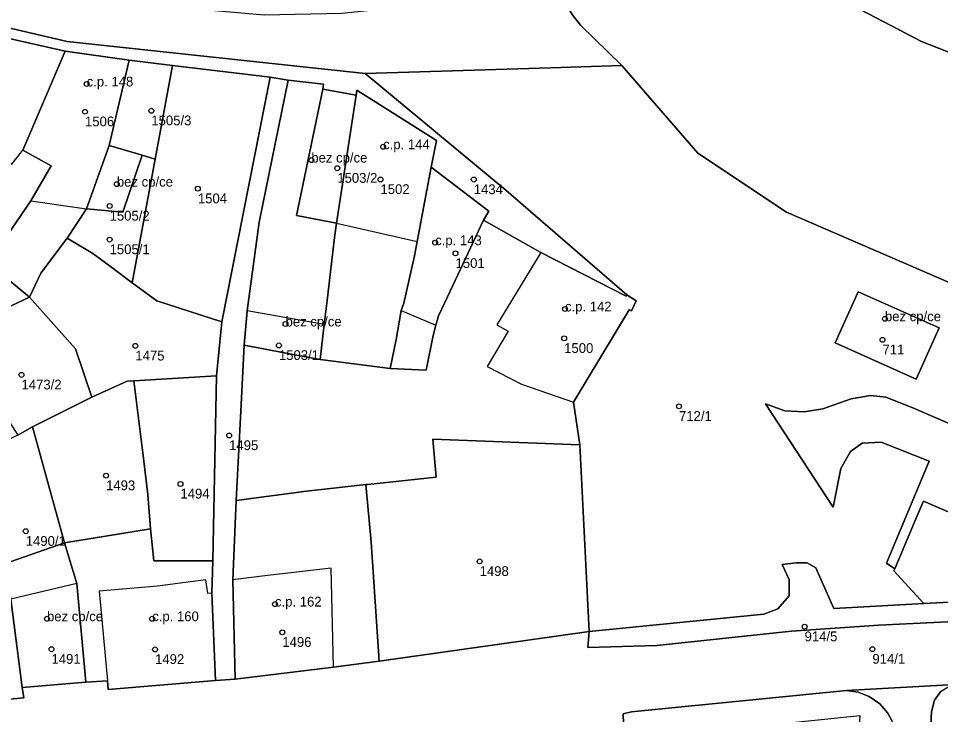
# Model space of a CAD drawing. Extents: x -878211 to -870363, y -1058464 to -1052522.
# Drawn here: x -874764.7 to -874670.5, y -1056309.4 to -1056238.3 of the extents above; entities that cross this region are included whole.
import ezdxf

# ---------------------------------------------------------------- set-up
doc = ezdxf.new("R2010")
doc.units = 0
for name, color, linetype in [('Vrstva 50', 7, 'Continuous'), ('Vrstva 51', 7, 'Continuous'), ('Vrstva 52', 7, 'Continuous')]:
    doc.layers.add(name, color=color, linetype=linetype)

msp = doc.modelspace()

# ---------------------------------------------------------------- linework, layer by layer
at = {"layer": 'Vrstva 50'}
for centre in [(-874757.7, -1056244.99994), (-874757.87, -1056247.82994), (-874751.1, -1056247.72994), (-874727.44, -1056251.40994), (-874734.77, -1056252.76994), (-874732.12, -1056253.59994), (-874727.71, -1056254.74994), (-874718.19, -1056254.75994), (-874754.62, -1056255.22994), (-874746.35, -1056255.68994), (-874755.36, -1056257.45994), (-874755.36, -1056260.88994), (-874722.13, -1056261.20994), (-874720.05, -1056262.29994), (-874708.88, -1056267.97994), (-874676.22, -1056268.97994), (-874737.4, -1056269.50994), (-874752.73, -1056271.74994), (-874738.08, -1056271.69994), (-874708.96, -1056270.97994), (-874676.47, -1056271.12994), (-874764.35, -1056274.70994), (-874697.24, -1056277.91994), (-874743.16, -1056280.89994), (-874755.72, -1056284.99994), (-874748.13, -1056285.84994), (-874763.92, -1056290.67994), (-874717.59, -1056293.75994), (-874738.48, -1056298.11994), (-874761.75, -1056299.61994), (-874751.01, -1056299.61994), (-874737.73, -1056300.99994), (-874684.42, -1056300.42994), (-874761.29, -1056302.72994), (-874750.72, -1056302.74994), (-874677.5, -1056302.71994)]:
    msp.add_circle(centre, 0.25, dxfattribs=at)
at = {"layer": 'Vrstva 51'}
for points in [[(-874779.01, -1056127.66), (-874780.45, -1056125.66), (-874793.17, -1056142.82), (-874792.46, -1056145.61), (-874788.37, -1056151.02), (-874786.78, -1056152.78), (-874770.12, -1056174.96), (-874761.29, -1056185.88), (-874747.51, -1056199.34), (-874747.04, -1056199.75), (-874740.87, -1056205.06), (-874728.32, -1056215.02), (-874719.92, -1056223.09), (-874716.4, -1056226.65), (-874716.73, -1056226.96), (-874713.06, -1056230.64), (-874711.1, -1056232.84), (-874708.16, -1056237.89), (-874707.28, -1056238.99), (-874703.07, -1056243.11), (-874695.31, -1056252.07), (-874686.26, -1056258.1), (-874668.18, -1056265.93)], [(-874664.15, -1056243.93), (-874672.49, -1056240.67), (-874680.25, -1056236.62), (-874679.58, -1056235.37), (-874681, -1056234.34), (-874681.77, -1056235.77), (-874686.72, -1056232.64), (-874692.16, -1056227.35), (-874692.89, -1056226.46), (-874696.8, -1056221.69), (-874698.33, -1056219.5), (-874701.45, -1056216.12), (-874704.89, -1056212.69), (-874716.6, -1056202), (-874718.85, -1056200.03), (-874730.46, -1056190.6), (-874737.21, -1056184.7), (-874741.58, -1056180.59), (-874749.63, -1056171.52), (-874755.19, -1056164.59)], [(-874666.81, -1056232.19), (-874672.71, -1056232.05), (-874675.44, -1056231.54), (-874681.17, -1056228.78), (-874687.74, -1056224.74), (-874687.96, -1056222.51), (-874692.89, -1056226.46), (-874692.16, -1056227.35), (-874686.72, -1056232.64), (-874681.77, -1056235.77), (-874681, -1056234.34), (-874679.58, -1056235.37), (-874680.25, -1056236.62), (-874672.49, -1056240.67), (-874664.15, -1056243.93)], [(-874773.13, -1056237.53), (-874759.69, -1056240.67), (-874729.27, -1056243.94), (-874710.36, -1056243.35), (-874703.07, -1056243.11), (-874707.28, -1056238.99), (-874708.16, -1056237.89), (-874711.1, -1056232.84), (-874718.62, -1056236.45), (-874731.64, -1056237.78), (-874739.6, -1056237.96), (-874752.36, -1056236.83), (-874752.29, -1056236.15), (-874752.81, -1056235.95), (-874754.35, -1056236.17), (-874758.8, -1056235.95), (-874774.8, -1056226.8)], [(-874773.17, -1056238.64), (-874759.89, -1056241.63), (-874753.36, -1056242.58), (-874748.93, -1056243.11), (-874738.98, -1056244.31), (-874737.15, -1056244.59), (-874733.54, -1056245.03), (-874733.6, -1056245.52), (-874730.2, -1056246.13), (-874730.12, -1056245.64), (-874721.98, -1056250.78), (-874722.55, -1056253.48), (-874716.65, -1056258), (-874717.19, -1056258.9), (-874711.34, -1056262.22), (-874702.64, -1056266.68), (-874702.55, -1056266.54), (-874714.91, -1056255.85), (-874729.27, -1056243.94), (-874759.69, -1056240.67), (-874773.13, -1056237.53)], [(-874668.18, -1056265.93), (-874686.26, -1056258.1), (-874695.31, -1056252.07), (-874703.07, -1056243.11), (-874710.36, -1056243.35), (-874729.27, -1056243.94), (-874714.91, -1056255.85), (-874702.55, -1056266.54), (-874701.61, -1056267.14), (-874702.1, -1056268.15), (-874702.32, -1056268.08), (-874708, -1056277.51), (-874707.37, -1056281.87), (-874706.42, -1056300.93), (-874688.58, -1056299.15), (-874687.15, -1056298.61), (-874686.01, -1056297.27), (-874686, -1056295.62), (-874686.71, -1056294.06), (-874685.26, -1056293.92), (-874684.17, -1056293.92), (-874683.29, -1056294.42), (-874681.42, -1056298.57), (-874672.26, -1056298.07), (-874675.3, -1056294.74), (-874675.22, -1056294.52), (-874676.05, -1056293.93), (-874671.71, -1056283.52), (-874676.6, -1056281.57), (-874678.55, -1056281.69), (-874679.75, -1056282.55), (-874680.71, -1056284.28), (-874681.49, -1056288.21), (-874688.4, -1056277.65), (-874686.45, -1056278.37), (-874684.45, -1056278.49), (-874682.55, -1056278.16), (-874679.67, -1056277.16), (-874677.7, -1056276.8), (-874676.13, -1056276.98), (-874673.36, -1056278.07), (-874669.06, -1056279.94)], [(-874669.06, -1056279.94), (-874673.36, -1056278.07), (-874676.13, -1056276.98), (-874677.7, -1056276.8), (-874679.67, -1056277.16), (-874682.55, -1056278.16), (-874684.45, -1056278.49), (-874686.45, -1056278.37), (-874688.4, -1056277.65), (-874681.49, -1056288.21), (-874680.71, -1056284.28), (-874679.75, -1056282.55), (-874678.55, -1056281.69), (-874676.6, -1056281.57), (-874671.71, -1056283.52), (-874676.05, -1056293.93), (-874675.22, -1056294.52), (-874672.96, -1056289.18), (-874672.29, -1056287.61), (-874662.04, -1056292.02)], [(-874665.6, -1056299.74), (-874676.84, -1056300.28), (-874685.76, -1056300.9), (-874699.51, -1056302.36), (-874706.55, -1056302.57), (-874706.42, -1056300.93), (-874727.85, -1056303.96), (-874732.52, -1056304.58), (-874742.55, -1056305.8), (-874744.54, -1056305.94), (-874755.51, -1056306.86), (-874755.58, -1056305.95), (-874757.77, -1056306.08), (-874764.27, -1056306.63), (-874764.11, -1056307.71), (-874773.64, -1056308.59), (-874777.22, -1056308.94), (-874782.12, -1056309.61)], [(-874702.87, -1056311.49), (-874702.94, -1056309.32), (-874702.09, -1056309.12), (-874680.13, -1056306.95), (-874668.48, -1056306.3)], [(-874668.48, -1056306.3), (-874680.13, -1056306.95), (-874678.94, -1056307.12), (-874677.84, -1056307.55), (-874676.75, -1056308.3), (-874675.91, -1056309.25), (-874675.49, -1056310.07)], [(-874670.03, -1056324.55), (-874671.48, -1056324.45), (-874671.44, -1056323.57), (-874671.98, -1056318.9), (-874671.48, -1056309.14), (-874671.17, -1056307.93), (-874670.54, -1056307.09)]]:
    msp.add_lwpolyline(points, dxfattribs=at)
for points in [[(-874774.24, -1056238.87), (-874775.52, -1056239.72), (-874777.2, -1056240.96), (-874773.75, -1056245.85), (-874771.66, -1056248.03), (-874773.68, -1056251.33), (-874770.95, -1056254.12), (-874768.89, -1056256.23), (-874770.94, -1056258.34), (-874771.83, -1056259.23), (-874767.75, -1056263.3), (-874765.9, -1056260.59), (-874763.4, -1056256.93), (-874761.33, -1056253.37), (-874764.21, -1056251.74), (-874759.89, -1056241.63), (-874773.17, -1056238.64)], [(-874777.2, -1056240.96), (-874783.25, -1056245.4), (-874777.38, -1056253.98), (-874766.66, -1056268.23), (-874763.52, -1056266.77), (-874767.75, -1056263.3), (-874771.83, -1056259.23), (-874770.94, -1056258.34), (-874768.89, -1056256.23), (-874770.95, -1056254.12), (-874773.68, -1056251.33), (-874771.66, -1056248.03), (-874773.75, -1056245.85)], [(-874759.89, -1056241.63), (-874764.21, -1056251.74), (-874761.33, -1056253.37), (-874763.4, -1056256.93), (-874765.9, -1056260.59), (-874767.75, -1056263.3), (-874763.52, -1056266.77), (-874762.37, -1056264.31), (-874759.7, -1056260.74), (-874757.73, -1056257.75), (-874755.42, -1056251.29), (-874753.36, -1056242.58)], [(-874753.36, -1056242.58), (-874755.42, -1056251.29), (-874752.05, -1056252.28), (-874750.7, -1056252.67), (-874748.93, -1056243.11)], [(-874750.7, -1056252.67), (-874753.04, -1056265.29), (-874750.54, -1056267.15), (-874743.89, -1056269.29), (-874738.98, -1056244.31), (-874748.93, -1056243.11)], [(-874743.89, -1056269.29), (-874744.46, -1056274.82), (-874744.84, -1056293.69), (-874744.91, -1056296.99), (-874744.54, -1056305.94), (-874742.55, -1056305.8), (-874742.79, -1056295.64), (-874742.44, -1056287.55), (-874741.96, -1056278.43), (-874741.61, -1056271.66), (-874741.31, -1056268.15), (-874740.09, -1056259.11), (-874737.15, -1056244.59), (-874738.98, -1056244.31)], [(-874736.29, -1056258.44), (-874733.6, -1056245.52), (-874733.54, -1056245.03), (-874737.15, -1056244.59), (-874740.09, -1056259.11), (-874741.31, -1056268.15), (-874741.61, -1056271.66), (-874736.08, -1056272.72), (-874733.87, -1056273.14), (-874733.46, -1056269.55), (-874733.16, -1056267.11), (-874732.39, -1056260.69), (-874732.2, -1056259.2)], [(-874730.2, -1056246.13), (-874733.6, -1056245.52), (-874736.29, -1056258.44), (-874732.2, -1056259.2)], [(-874730.2, -1056246.13), (-874732.2, -1056259.2), (-874732.39, -1056260.69), (-874733.16, -1056267.11), (-874733.46, -1056269.55), (-874733.87, -1056273.14), (-874726.73, -1056274.07), (-874726.11, -1056271.09), (-874725.59, -1056268.13), (-874725.33, -1056267.4), (-874724.25, -1056262.55), (-874723.97, -1056261.08), (-874722.55, -1056253.48), (-874721.98, -1056250.78), (-874730.12, -1056245.64)], [(-874757.73, -1056257.75), (-874754.01, -1056258.08), (-874752.05, -1056252.28), (-874755.42, -1056251.29)], [(-874752.05, -1056252.28), (-874754.01, -1056258.08), (-874757.73, -1056257.75), (-874759.7, -1056260.74), (-874757.06, -1056262.3), (-874755.13, -1056263.74), (-874753.04, -1056265.29), (-874750.7, -1056252.67)], [(-874725.59, -1056268.13), (-874726.11, -1056271.09), (-874726.73, -1056274.07), (-874723.05, -1056274.22), (-874722.35, -1056270.7), (-874722.06, -1056269.63), (-874721.79, -1056268.68), (-874720.87, -1056266.73), (-874717.19, -1056258.9), (-874716.65, -1056258), (-874722.55, -1056253.48), (-874723.97, -1056261.08), (-874724.25, -1056262.55), (-874725.33, -1056267.4)], [(-874726.73, -1056274.07), (-874733.87, -1056273.14), (-874736.08, -1056272.72), (-874741.61, -1056271.66), (-874741.96, -1056278.43), (-874742.44, -1056287.55), (-874735.25, -1056286.6), (-874733.12, -1056286.36), (-874729.2, -1056285.92), (-874729, -1056285.9), (-874722.02, -1056285.14), (-874722.37, -1056281.26), (-874707.37, -1056281.87), (-874708, -1056277.51), (-874702.32, -1056268.08), (-874702.1, -1056268.15), (-874701.61, -1056267.14), (-874702.55, -1056266.54), (-874702.64, -1056266.68), (-874711.34, -1056262.22), (-874717.19, -1056258.9), (-874720.87, -1056266.73), (-874721.79, -1056268.68), (-874722.06, -1056269.63), (-874722.35, -1056270.7), (-874723.05, -1056274.22)], [(-874762.37, -1056264.31), (-874763.52, -1056266.77), (-874758.84, -1056272.05), (-874757.19, -1056276.98), (-874753.58, -1056275.36), (-874752.88, -1056275.32), (-874744.46, -1056274.82), (-874743.89, -1056269.29), (-874750.54, -1056267.15), (-874753.04, -1056265.29), (-874755.13, -1056263.74), (-874757.06, -1056262.3), (-874759.7, -1056260.74)], [(-874767.46, -1056276.69), (-874764.73, -1056280.88), (-874763.22, -1056280.01), (-874757.19, -1056276.98), (-874758.84, -1056272.05), (-874763.52, -1056266.77), (-874766.66, -1056268.23), (-874771.33, -1056270.93)], [(-874670.68, -1056269.89), (-874673.02, -1056275.14), (-874681.3, -1056271.45), (-874678.95, -1056266.21)], [(-874670.68, -1056269.89), (-874678.95, -1056266.21), (-874681.3, -1056271.45), (-874673.02, -1056275.14)], [(-874751.45, -1056286.92), (-874751.96, -1056282.66), (-874752.88, -1056275.32), (-874753.58, -1056275.36), (-874757.19, -1056276.98), (-874763.22, -1056280.01), (-874759.98, -1056291.86), (-874751.2, -1056290.43)], [(-874744.46, -1056274.82), (-874752.88, -1056275.32), (-874751.96, -1056282.66), (-874751.45, -1056286.92), (-874751.2, -1056290.43), (-874750.84, -1056293.71), (-874744.84, -1056293.69)], [(-874764.73, -1056280.88), (-874775.27, -1056285.79), (-874774.59, -1056288.09), (-874774.04, -1056290.94), (-874772.65, -1056290.67), (-874771.32, -1056290.37), (-874771.51, -1056289.42), (-874768.96, -1056288.26), (-874769.35, -1056287.34), (-874768.05, -1056286.78), (-874766.82, -1056289.6), (-874767.89, -1056290.01), (-874766.1, -1056294), (-874759.98, -1056291.86), (-874763.22, -1056280.01)], [(-874729.2, -1056285.92), (-874728.66, -1056291.78), (-874727.85, -1056303.96), (-874706.42, -1056300.93), (-874707.37, -1056281.87), (-874722.37, -1056281.26), (-874722.02, -1056285.14), (-874729, -1056285.9)], [(-874769.35, -1056287.34), (-874768.96, -1056288.26), (-874771.51, -1056289.42), (-874771.32, -1056290.37), (-874772.65, -1056290.67), (-874774.04, -1056290.94), (-874774.59, -1056288.09), (-874775.27, -1056285.79), (-874776.96, -1056286.51), (-874775.56, -1056294.88), (-874774.94, -1056298.49), (-874774.36, -1056303.02), (-874773.64, -1056308.59), (-874764.11, -1056307.71), (-874764.27, -1056306.63), (-874765.45, -1056297.61), (-874766.1, -1056294), (-874767.89, -1056290.01), (-874766.82, -1056289.6), (-874768.05, -1056286.78)], [(-874742.44, -1056287.55), (-874742.79, -1056295.64), (-874742.55, -1056305.8), (-874732.52, -1056304.58), (-874727.85, -1056303.96), (-874728.66, -1056291.78), (-874729.2, -1056285.92), (-874733.12, -1056286.36), (-874735.25, -1056286.6)], [(-874672.26, -1056298.07), (-874666.99, -1056297.78), (-874650.44, -1056297.75), (-874650.43, -1056298.45), (-874650.22, -1056298.54), (-874649.68, -1056293.14), (-874651.98, -1056293.33), (-874654.17, -1056293.51), (-874657.17, -1056293.22), (-874659.15, -1056292.83), (-874662.04, -1056292.02), (-874672.29, -1056287.61), (-874672.96, -1056289.18), (-874675.22, -1056294.52), (-874675.3, -1056294.74)], [(-874755.51, -1056306.86), (-874744.54, -1056305.94), (-874744.91, -1056296.99), (-874744.84, -1056293.69), (-874750.84, -1056293.71), (-874751.2, -1056290.43), (-874759.98, -1056291.86), (-874758.71, -1056296.02), (-874757.77, -1056306.08), (-874755.58, -1056305.95)], [(-874766.1, -1056294), (-874765.45, -1056297.61), (-874764.27, -1056306.63), (-874757.77, -1056306.08), (-874758.71, -1056296.02), (-874759.98, -1056291.86)], [(-874706.42, -1056300.93), (-874706.55, -1056302.57), (-874699.51, -1056302.36), (-874685.76, -1056300.9), (-874676.84, -1056300.28), (-874665.6, -1056299.74), (-874650.2, -1056299.73), (-874650.22, -1056298.54), (-874650.43, -1056298.45), (-874650.44, -1056297.75), (-874666.99, -1056297.78), (-874672.26, -1056298.07), (-874681.42, -1056298.57), (-874683.29, -1056294.42), (-874684.17, -1056293.92), (-874685.26, -1056293.92), (-874686.71, -1056294.06), (-874686, -1056295.62), (-874686.01, -1056297.27), (-874687.15, -1056298.61), (-874688.58, -1056299.15)], [(-874671.98, -1056318.9), (-874671.44, -1056323.57), (-874671.48, -1056324.45), (-874670.03, -1056324.55), (-874669.89, -1056322.45), (-874669.04, -1056309.97), (-874667.58, -1056308.54), (-874661.06, -1056308.27), (-874652.7, -1056307.88), (-874639.53, -1056307.88), (-874634.61, -1056308.52), (-874634.55, -1056306.42), (-874639.68, -1056306.57), (-874647.74, -1056306.28), (-874658.74, -1056306.11), (-874668.48, -1056306.3), (-874669.52, -1056306.48), (-874670.54, -1056307.09), (-874671.17, -1056307.93), (-874671.48, -1056309.14)], [(-874677.71, -1056315.12), (-874675.74, -1056315.2), (-874675.29, -1056314.7), (-874675.14, -1056311.95), (-874675.22, -1056310.99), (-874675.49, -1056310.07), (-874675.91, -1056309.25), (-874676.75, -1056308.3), (-874677.84, -1056307.55), (-874678.94, -1056307.12), (-874680.13, -1056306.95), (-874702.09, -1056309.12), (-874702.94, -1056309.32), (-874702.87, -1056311.49), (-874699.75, -1056311.33), (-874686.97, -1056310.34), (-874678.78, -1056309.49), (-874679.78, -1056325.47), (-874678.39, -1056325.55)]]:
    msp.add_lwpolyline(points, close=True, dxfattribs=at)
at = {"layer": 'Vrstva 52'}
for points in [[(-874777.2, -1056240.96), (-874773.75, -1056245.85), (-874771.66, -1056248.03), (-874769.44, -1056251.38), (-874768.65, -1056250.32), (-874765.34, -1056253.19), (-874764.21, -1056251.74), (-874759.89, -1056241.63), (-874773.17, -1056238.64), (-874774.24, -1056238.87), (-874775.52, -1056239.72)], [(-874759.89, -1056241.63), (-874764.21, -1056251.74), (-874761.33, -1056253.37), (-874763.4, -1056256.93), (-874757.73, -1056257.75), (-874755.42, -1056251.29), (-874753.36, -1056242.58)], [(-874736.29, -1056258.44), (-874732.2, -1056259.2), (-874730.2, -1056246.13), (-874733.6, -1056245.52)], [(-874732.2, -1056259.2), (-874724.85, -1056260.88), (-874723.97, -1056261.08), (-874722.55, -1056253.48), (-874721.98, -1056250.78), (-874730.12, -1056245.64), (-874730.2, -1056246.13)], [(-874755.42, -1056251.29), (-874757.73, -1056257.75), (-874754.01, -1056258.08), (-874752.05, -1056252.28)], [(-874716.65, -1056258), (-874722.55, -1056253.48), (-874723.97, -1056261.08), (-874724.25, -1056262.55), (-874725.33, -1056267.4), (-874725.59, -1056268.13), (-874722.06, -1056269.63), (-874721.79, -1056268.68), (-874720.87, -1056266.73), (-874717.19, -1056258.9)], [(-874714.68, -1056270.24), (-874716.82, -1056273.84), (-874713.32, -1056275.65), (-874708, -1056277.51), (-874702.32, -1056268.08), (-874702.1, -1056268.15), (-874701.61, -1056267.14), (-874702.55, -1056266.54), (-874702.64, -1056266.68), (-874711.34, -1056262.22), (-874715.83, -1056269.61)], [(-874681.3, -1056271.45), (-874673.02, -1056275.14), (-874670.68, -1056269.89), (-874678.95, -1056266.21)], [(-874733.46, -1056269.55), (-874741.31, -1056268.15), (-874741.61, -1056271.66), (-874736.08, -1056272.72), (-874733.87, -1056273.14)], [(-874775.35, -1056285.53), (-874777.13, -1056286.1), (-874776.96, -1056286.51), (-874775.56, -1056294.88), (-874774.94, -1056298.49), (-874774.36, -1056303.02), (-874773.64, -1056308.59), (-874764.11, -1056307.71), (-874764.27, -1056306.63), (-874765.45, -1056297.61), (-874766.1, -1056294), (-874767.89, -1056290.01), (-874767.97, -1056289.79), (-874771.32, -1056290.37), (-874772.65, -1056290.67), (-874774.04, -1056290.94), (-874774.59, -1056288.09), (-874775.27, -1056285.79)], [(-874739.51, -1056295.25), (-874742.79, -1056295.64), (-874742.55, -1056305.8), (-874732.52, -1056304.58), (-874732.76, -1056294.44)], [(-874765.45, -1056297.61), (-874764.27, -1056306.63), (-874757.77, -1056306.08), (-874758.71, -1056296.02)], [(-874756.41, -1056296.81), (-874755.58, -1056305.95), (-874755.51, -1056306.86), (-874744.54, -1056305.94), (-874744.91, -1056296.99), (-874745.35, -1056297.05), (-874745.55, -1056295.64), (-874750.48, -1056296.28)]]:
    msp.add_lwpolyline(points, close=True, dxfattribs=at)

# ---------------------------------------------------------------- texts
at = {"layer": 'Vrstva 50'}
for s, p in [('c.p. 148', (-874757.7, -1056245.25)), ('1506', (-874757.87, -1056249.319)), ('1505/3', (-874751.1, -1056249.219)), ('c.p. 144', (-874727.44, -1056251.659)), ('bez cp/ce', (-874734.77, -1056253.02)), ('bez cp/ce', (-874754.62, -1056255.48)), ('1503/2', (-874732.12, -1056255.089)), ('1502', (-874727.71, -1056256.239)), ('1434', (-874718.19, -1056256.249)), ('1504', (-874746.35, -1056257.179)), ('1505/2', (-874755.36, -1056258.949)), ('c.p. 143', (-874722.13, -1056261.46)), ('1505/1', (-874755.36, -1056262.379)), ('1501', (-874720.05, -1056263.789)), ('c.p. 142', (-874708.88, -1056268.23)), ('bez cp/ce', (-874737.4, -1056269.76)), ('bez cp/ce', (-874676.22, -1056269.23)), ('1500', (-874708.96, -1056272.469)), ('1475', (-874752.73, -1056273.239)), ('1503/1', (-874738.08, -1056273.189)), ('711', (-874676.47, -1056272.619)), ('1473/2', (-874764.35, -1056276.199)), ('712/1', (-874697.24, -1056279.409)), ('1495', (-874743.16, -1056282.389)), ('1493', (-874755.72, -1056286.489)), ('1494', (-874748.13, -1056287.339)), ('1490/1', (-874763.92, -1056292.169)), ('1498', (-874717.59, -1056295.249)), ('c.p. 162', (-874738.48, -1056298.37)), ('bez cp/ce', (-874761.75, -1056299.87)), ('c.p. 160', (-874751.01, -1056299.87)), ('1496', (-874737.73, -1056302.489)), ('914/5', (-874684.42, -1056301.919)), ('1491', (-874761.29, -1056304.219)), ('1492', (-874750.72, -1056304.239)), ('914/1', (-874677.5, -1056304.209))]:
    msp.add_text(s, height=0.999996, dxfattribs=at).set_placement(p)

doc.saveas('drawing.dxf')
